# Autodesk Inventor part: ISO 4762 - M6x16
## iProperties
CLASSIFICATION: 311615
MANUFACTURER: ISO Système de normes
Author: robert
Shininess: 20.0
Angle Display Precision: 2
Document Length Units: 11269
Document Angle Units: 11283
Document Time Units: 11279
Document Mass Units: 11290
Document Length Units Precision: 3
Document Angle Units Precision: 2
Compacted: True
PropertySet Name: _Private Model Information
Created: 2002-06
Part Number: ISO 4762 - M6x16
Material: Par défaut
Catalog Web Link: file:///C:/Program Files/Autodesk/Inventor 5/Content/Iso/index.htm?doNavigateId=932883F9-F3A7-4770-8571-ED868C9DA26C|EBC54E0E0DF64B0EA7FF8E8452D543C5|true
Description: Vis cylindrique à six pans creux
Document SubType Name: Standard Catalog Part
Standard: ISO 4762 - M6x16
Designer: robert
Control State: 0
Master: False
Checked Out: False
PropertySet Name: Design Tracking Control
Density: 0.0
Volumn: 0.0
Area: 0.0
PropertySet Name: Model Information
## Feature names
1. Base1
